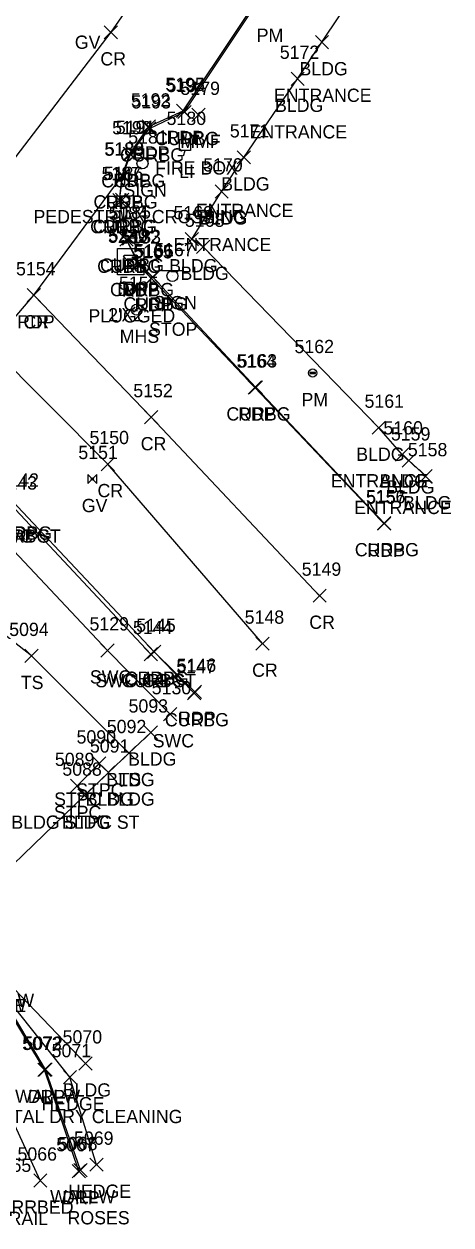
# Model space of a CAD drawing. Extents: x 1618146 to 1620418, y 640749 to 641927.
# Drawn here: x 1620347.9 to 1620412.3, y 640855.4 to 641036.5 of the extents above; entities that cross this region are included whole.
import ezdxf

# ---------------------------------------------------------------- set-up
doc = ezdxf.new("R2010")
doc.units = 0
for name, color, linetype in [('D_A', 7, 'Continuous'), ('D_C', 7, 'Continuous'), ('D_I', 7, 'Continuous'), ('D_TIC', 7, 'Continuous'), ('DS', 7, 'Continuous'), ('L_A', 7, 'Continuous'), ('L_C', 7, 'Continuous'), ('L_I', 7, 'Continuous'), ('L_TIC', 7, 'Continuous'), ('LAHR', 7, 'Continuous'), ('LBC', 7, 'Continuous'), ('LBF', 7, 'Continuous'), ('LELB', 7, 'Continuous'), ('LW', 7, 'Continuous'), ('P_A', 7, 'Continuous'), ('P_I', 7, 'Continuous'), ('P_TIC', 7, 'Continuous'), ('PET', 7, 'Continuous'), ('PRC', 7, 'Continuous'), ('R_A', 7, 'Continuous'), ('R_I', 7, 'Continuous'), ('R_TIC', 7, 'Continuous'), ('RC', 7, 'Continuous'), ('RDP', 7, 'Continuous'), ('RRB', 7, 'Continuous'), ('RSW', 7, 'Continuous'), ('S_A', 7, 'Continuous'), ('S_C', 7, 'Continuous'), ('S_I', 7, 'Continuous'), ('SPM', 7, 'Continuous'), ('SSGN', 7, 'Continuous'), ('U_A', 7, 'Continuous'), ('U_I', 7, 'Continuous'), ('ULP', 7, 'Continuous'), ('USMH', 7, 'Continuous'), ('UWV', 7, 'Continuous')]:
    doc.layers.add(name, color=color, linetype=linetype)

msp = doc.modelspace()

# ---------------------------------------------------------------- linework, layer by layer
at = {"layer": 'D_TIC'}
for points in [[(1620362.87, 640999.49), (1620364.87, 641001.49)], [(1620364.87, 640999.49), (1620362.87, 641001.49)]]:
    msp.add_lwpolyline(points, dxfattribs=at)
at = {"layer": 'DS'}
for p, q in [((1620362.02, 641002.65), (1620366.02, 641002.65)), ((1620362.02, 640998.65), (1620362.02, 641002.65)), ((1620366.02, 641002.65), (1620366.02, 640998.65)), ((1620363.02, 640999.65), (1620363.02, 641001.65)), ((1620363.02, 641001.65), (1620365.02, 641001.65)), ((1620364.03, 641000.65), (1620364.03, 641000.65)), ((1620364.03, 641000.65), (1620364.03, 641000.65)), ((1620365.02, 641001.65), (1620365.02, 640999.65)), ((1620365.02, 640999.65), (1620363.02, 640999.65)), ((1620366.02, 640998.65), (1620362.02, 640998.65))]:
    msp.add_line(p, q, dxfattribs=at)
at = {"layer": 'L_TIC'}
for points in [[(1620391.85, 641032.74), (1620393.85, 641034.74)], [(1620393.85, 641032.74), (1620391.85, 641034.74)], [(1620388.18, 641027.23), (1620390.18, 641029.23)], [(1620390.18, 641027.23), (1620388.18, 641029.23)], [(1620373.22, 641021.79), (1620375.22, 641023.79)], [(1620375.22, 641021.79), (1620373.22, 641023.79)], [(1620380.08, 641015.38), (1620382.08, 641017.38)], [(1620382.08, 641015.38), (1620380.08, 641017.38)], [(1620376.73, 641010.25), (1620378.73, 641012.25)], [(1620378.73, 641010.25), (1620376.73, 641012.25)], [(1620372.23, 641003.05), (1620374.23, 641005.05)], [(1620374.23, 641003.05), (1620372.23, 641005.05)], [(1620373.93, 641001.91), (1620375.93, 641003.91)], [(1620375.93, 641001.91), (1620373.93, 641003.91)], [(1620400.43, 640974.63), (1620402.43, 640976.63)], [(1620402.43, 640974.63), (1620400.43, 640976.63)], [(1620403.94, 640970.61), (1620405.94, 640972.61)], [(1620405.94, 640970.61), (1620403.94, 640972.61)], [(1620404.94, 640969.7), (1620406.94, 640971.7)], [(1620406.94, 640969.7), (1620404.94, 640971.7)], [(1620407.48, 640967.32), (1620409.48, 640969.32)], [(1620409.48, 640967.32), (1620407.48, 640969.32)], [(1620348.05, 640940.23), (1620350.05, 640942.23)], [(1620350.05, 640940.23), (1620348.05, 640942.23)], [(1620366.04, 640928.69), (1620368.04, 640930.69)], [(1620368.04, 640928.69), (1620366.04, 640930.69)], [(1620362.76, 640925.59), (1620364.76, 640927.59)], [(1620364.76, 640925.59), (1620362.76, 640927.59)], [(1620362.76, 640925.59), (1620364.76, 640927.59)], [(1620364.76, 640925.59), (1620362.76, 640927.59)], [(1620358.29, 640924.02), (1620360.29, 640926.02)], [(1620360.29, 640924.02), (1620358.29, 640926.02)], [(1620359.65, 640922.65), (1620361.65, 640924.65)], [(1620361.65, 640922.65), (1620359.65, 640924.65)], [(1620359.65, 640922.65), (1620361.65, 640924.65)], [(1620361.65, 640922.65), (1620359.65, 640924.65)], [(1620354.94, 640920.64), (1620356.94, 640922.64)], [(1620356.94, 640920.64), (1620354.94, 640922.64)], [(1620356.06, 640919.17), (1620358.06, 640921.17)], [(1620358.06, 640919.17), (1620356.06, 640921.17)], [(1620356.06, 640919.17), (1620358.06, 640921.17)], [(1620358.06, 640919.17), (1620356.06, 640921.17)], [(1620350.18, 640877.87), (1620352.18, 640879.87)], [(1620352.18, 640877.87), (1620350.18, 640879.87)], [(1620356.19, 640878.8), (1620358.19, 640880.8)], [(1620358.19, 640878.8), (1620356.19, 640880.8)], [(1620353.87, 640876.73), (1620355.87, 640878.73)], [(1620355.87, 640876.73), (1620353.87, 640878.73)], [(1620357.88, 640863.54), (1620359.88, 640865.54)], [(1620359.88, 640863.54), (1620357.88, 640865.54)], [(1620355.45, 640862.73), (1620357.45, 640864.73)], [(1620357.45, 640862.73), (1620355.45, 640864.73)]]:
    msp.add_lwpolyline(points, dxfattribs=at)
at = {"layer": 'LAHR'}
msp.add_lwpolyline([(1620358.88, 640864.54), (1620354.87, 640877.73), (1620343.03, 640892.53)], dxfattribs=at)
at = {"layer": 'LBC'}
for points in [[(1620408.48, 640968.32), (1620405.94, 640970.7), (1620404.94, 640971.61), (1620401.43, 640975.63), (1620374.93, 641002.91), (1620373.23, 641004.05), (1620377.73, 641011.25), (1620381.08, 641016.38), (1620389.18, 641028.23), (1620392.85, 641033.74), (1620400.72, 641045.56), (1620404.21, 641050.79), (1620408.66, 641057.75)], [(1620357.19, 640879.8), (1620344.24, 640893.33), (1620344.13, 640893.45), (1620337.08, 640900.88), (1620357.06, 640920.17), (1620360.65, 640923.65), (1620363.76, 640926.59), (1620367.04, 640929.69)]]:
    msp.add_lwpolyline(points, dxfattribs=at)
at = {"layer": 'LBF'}
msp.add_lwpolyline([(1620357.06, 640920.17), (1620355.94, 640921.64), (1620359.29, 640925.02), (1620360.65, 640923.65)], dxfattribs=at)
at = {"layer": 'LELB'}
msp.add_lwpolyline([(1620363.76, 640926.59), (1620349.05, 640941.23), (1620337.14, 640950.53)], dxfattribs=at)
at = {"layer": 'LW'}
msp.add_lwpolyline([(1620356.45, 640863.73), (1620351.18, 640878.87), (1620343.03, 640892.53), (1620344.24, 640893.33)], dxfattribs=at)
at = {"layer": 'P_TIC'}
for points in [[(1620360.02, 641034.23), (1620362.02, 641036.23)], [(1620362.02, 641034.23), (1620360.02, 641036.23)], [(1620370.94, 641022.38), (1620372.94, 641024.38)], [(1620372.94, 641022.38), (1620370.94, 641024.38)], [(1620365.74, 641020.04), (1620367.74, 641022.04)], [(1620367.74, 641020.04), (1620365.74, 641022.04)], [(1620362.9, 641015.91), (1620364.9, 641017.91)], [(1620364.9, 641015.91), (1620362.9, 641017.91)], [(1620361.74, 641012.62), (1620363.74, 641014.62)], [(1620363.74, 641012.62), (1620361.74, 641014.62)], [(1620361.74, 641012.62), (1620363.74, 641014.62)], [(1620363.74, 641012.62), (1620361.74, 641014.62)], [(1620361.32, 641008.94), (1620363.32, 641010.94)], [(1620363.32, 641008.94), (1620361.32, 641010.94)], [(1620362.39, 641002.97), (1620364.39, 641004.97)], [(1620364.39, 641002.97), (1620362.39, 641004.97)], [(1620364.19, 640999.38), (1620366.19, 641001.38)], [(1620366.19, 640999.38), (1620364.19, 641001.38)], [(1620366.13, 640997.15), (1620368.13, 640999.15)], [(1620368.13, 640997.15), (1620366.13, 640999.15)], [(1620348.43, 640994.59), (1620350.43, 640996.59)], [(1620350.43, 640994.59), (1620348.43, 640996.59)], [(1620348.43, 640994.59), (1620350.43, 640996.59)], [(1620350.43, 640994.59), (1620348.43, 640996.59)], [(1620381.71, 640980.68), (1620383.71, 640982.68)], [(1620383.71, 640980.68), (1620381.71, 640982.68)], [(1620366.1, 640976.22), (1620368.1, 640978.22)], [(1620368.1, 640976.22), (1620366.1, 640978.22)], [(1620359.59, 640969.15), (1620361.59, 640971.15)], [(1620361.59, 640969.15), (1620359.59, 640971.15)], [(1620401.21, 640960.16), (1620403.21, 640962.16)], [(1620403.21, 640960.16), (1620401.21, 640962.16)], [(1620391.5, 640949.31), (1620393.5, 640951.31)], [(1620393.5, 640949.31), (1620391.5, 640951.31)], [(1620366.54, 640940.86), (1620368.54, 640942.86)], [(1620368.54, 640940.86), (1620366.54, 640942.86)], [(1620382.89, 640942.08), (1620384.89, 640944.08)], [(1620384.89, 640942.08), (1620382.89, 640944.08)], [(1620372.7, 640934.83), (1620374.7, 640936.83)], [(1620374.7, 640934.83), (1620372.7, 640936.83)]]:
    msp.add_lwpolyline(points, dxfattribs=at)
at = {"layer": 'PET'}
for points in [[(1620301.6, 640941.89), (1620306.67, 640947.65), (1620308.05, 640949.03), (1620313.72, 640955.55), (1620317.97, 640960.23), (1620327.2, 640970.29), (1620342.84, 640987.93), (1620349.43, 640995.59), (1620362.74, 641013.62), (1620363.9, 641016.91), (1620366.74, 641021.04), (1620371.94, 641023.38), (1620397.59, 641061.89), (1620399.29, 641063.9)], [(1620402.21, 640961.16), (1620382.71, 640981.68), (1620367.13, 640998.15), (1620365.19, 641000.38), (1620363.39, 641003.97), (1620362.32, 641009.94), (1620362.74, 641013.62)], [(1620327.2, 640970.29), (1620330.45, 640972.78), (1620333.39, 640973.27), (1620335.69, 640973.14), (1620337.31, 640972.69), (1620340.81, 640970.42), (1620346.94, 640963.75), (1620367.54, 640941.86), (1620373.7, 640935.83)]]:
    msp.add_lwpolyline(points, dxfattribs=at)
at = {"layer": 'PRC'}
for points in [[(1620386.4, 641071.71), (1620361.02, 641035.23), (1620336.24, 641002.91), (1620316.22, 640977.17), (1620300.32, 640960.31), (1620296.61, 640956.78), (1620272.86, 640927.85), (1620252.18, 640901.58), (1620233.9, 640877.59)], [(1620392.5, 640950.31), (1620367.1, 640977.22), (1620349.43, 640995.59)], [(1620383.89, 640943.08), (1620360.59, 640970.15), (1620342.84, 640987.93)]]:
    msp.add_lwpolyline(points, dxfattribs=at)
at = {"layer": 'R_TIC'}
for points in [[(1620371.11, 641022.22), (1620373.11, 641024.22)], [(1620373.11, 641022.22), (1620371.11, 641024.22)], [(1620365.83, 641019.75), (1620367.83, 641021.75)], [(1620367.83, 641019.75), (1620365.83, 641021.75)], [(1620363, 641015.85), (1620365, 641017.85)], [(1620365, 641015.85), (1620363, 641017.85)], [(1620361.82, 641012.67), (1620363.82, 641014.67)], [(1620363.82, 641012.67), (1620361.82, 641014.67)], [(1620361.32, 641008.94), (1620363.32, 641010.94)], [(1620363.32, 641008.94), (1620361.32, 641010.94)], [(1620361.72, 641008.97), (1620363.72, 641010.97)], [(1620363.72, 641008.97), (1620361.72, 641010.97)], [(1620362.39, 641002.97), (1620364.39, 641004.97)], [(1620364.39, 641002.97), (1620362.39, 641004.97)], [(1620362.81, 641003.14), (1620364.81, 641005.14)], [(1620364.81, 641003.14), (1620362.81, 641005.14)], [(1620364.32, 640999.45), (1620366.32, 641001.45)], [(1620366.32, 640999.45), (1620364.32, 641001.45)], [(1620366.34, 640997.3), (1620368.34, 640999.3)], [(1620368.34, 640997.3), (1620366.34, 640999.3)], [(1620381.87, 640980.71), (1620383.87, 640982.71)], [(1620383.87, 640980.71), (1620381.87, 640982.71)], [(1620401.22, 640960.24), (1620403.22, 640962.24)], [(1620403.22, 640960.24), (1620401.22, 640962.24)], [(1620359.51, 640941.06), (1620361.51, 640943.06)], [(1620361.51, 640941.06), (1620359.51, 640943.06)], [(1620366.54, 640940.86), (1620368.54, 640942.86)], [(1620368.54, 640940.86), (1620366.54, 640942.86)], [(1620366.05, 640940.51), (1620368.05, 640942.51)], [(1620368.05, 640940.51), (1620366.05, 640942.51)], [(1620366.05, 640940.51), (1620368.05, 640942.51)], [(1620368.05, 640940.51), (1620366.05, 640942.51)], [(1620372.58, 640934.61), (1620374.58, 640936.61)], [(1620374.58, 640934.61), (1620372.58, 640936.61)], [(1620368.97, 640931.44), (1620370.97, 640933.44)], [(1620370.97, 640931.44), (1620368.97, 640933.44)], [(1620350.01, 640877.82), (1620352.01, 640879.82)], [(1620352.01, 640877.82), (1620350.01, 640879.82)], [(1620349.4, 640861.15), (1620351.4, 640863.15)], [(1620351.4, 640861.15), (1620349.4, 640863.15)], [(1620355.19, 640862.55), (1620357.19, 640864.55)], [(1620357.19, 640862.55), (1620355.19, 640864.55)]]:
    msp.add_lwpolyline(points, dxfattribs=at)
at = {"layer": 'RC'}
for points in [[(1620362.72, 641009.97), (1620362.32, 641009.94), (1620362.82, 641013.67), (1620364, 641016.85), (1620366.83, 641020.75), (1620372.11, 641023.22), (1620397.73, 641061.74), (1620399.29, 641063.9), (1620399.42, 641063.74)], [(1620402.22, 640961.24), (1620382.87, 640981.71), (1620367.34, 640998.3), (1620365.32, 641000.45), (1620363.39, 641003.97), (1620363.81, 641004.14)], [(1620367.05, 640941.51), (1620367.54, 640941.86), (1620373.58, 640935.61)]]:
    msp.add_lwpolyline(points, dxfattribs=at)
at = {"layer": 'RDP'}
msp.add_lwpolyline([(1620356.19, 640863.55), (1620351.01, 640878.82), (1620342.67, 640892.6), (1620344.13, 640893.45)], dxfattribs=at)
at = {"layer": 'RRB'}
msp.add_lwpolyline([(1620350.4, 640862.15), (1620333.7, 640898.49), (1620311.06, 640944.94)], dxfattribs=at)
at = {"layer": 'RSW'}
for points in [[(1620308.05, 640949.03), (1620311.06, 640944.94), (1620322.85, 640957.65), (1620323.38, 640958.18), (1620330.34, 640965.74), (1620332.11, 640966.82), (1620333.44, 640967.5), (1620336.86, 640966.1), (1620338.93, 640962.95), (1620340.87, 640962.9), (1620360.51, 640942.06), (1620369.97, 640932.44)], [(1620346.65, 640963.3), (1620367.05, 640941.51)]]:
    msp.add_lwpolyline(points, dxfattribs=at)
at = {"layer": 'SPM'}
msp.add_lwpolyline([(1620391.03, 640983.78), (1620391.86, 640983.78), (1620391.86, 640983.95), (1620391.03, 640983.95)], close=True, dxfattribs=at)
msp.add_circle((1620391.45, 640983.87), 0.625, dxfattribs=at)
at = {"layer": 'SSGN'}
for p, q in [((1620364.15, 641016.3), (1620367.48, 641016.3)), ((1620365.8, 641015.47), (1620365.8, 641015.47)), ((1620368.67, 640999.33), (1620372, 640999.33)), ((1620370.31, 640998.5), (1620370.31, 640998.5))]:
    msp.add_line(p, q, dxfattribs=at)
for centre in [(1620365.8, 641015.47), (1620370.31, 640998.5)]:
    msp.add_circle(centre, 0.833, dxfattribs=at)
at = {"layer": 'ULP'}
for p, q in [((1620371.38, 641017.43), (1620371.38, 641019.09)), ((1620371.38, 641019.09), (1620373.05, 641019.09)), ((1620372.38, 641019.93), (1620372.21, 641019.09)), ((1620373.05, 641019.09), (1620373.05, 641017.43)), ((1620373.05, 641017.43), (1620371.38, 641017.43)), ((1620371.96, 641016.59), (1620372.21, 641017.43)), ((1620372.21, 641018.26), (1620372.21, 641018.26))]:
    msp.add_line(p, q, dxfattribs=at)
at = {"layer": 'USMH'}
for p, q in [((1620364.94, 640993.42), (1620364.94, 640993.42)), ((1620365.78, 640993.42), (1620365.78, 640993.42))]:
    msp.add_line(p, q, dxfattribs=at)
msp.add_circle((1620364.94, 640993.42), 0.833, dxfattribs=at)
at = {"layer": 'UWV'}
for p, q in [((1620357.58, 640968.57), (1620358.92, 640967.23)), ((1620358.92, 640968.57), (1620357.58, 640967.23))]:
    msp.add_line(p, q, dxfattribs=at)
for points in [[(1620357.58, 640968.57), (1620357.58, 640967.23)], [(1620358.92, 640967.23), (1620358.92, 640968.57)]]:
    msp.add_lwpolyline(points, dxfattribs=at)
msp.add_circle((1620358.25, 640967.9), 0.167, dxfattribs=at)

# ---------------------------------------------------------------- texts
at = {"layer": 'D_A'}
for s, p in [('DIB', (1620361.97, 640995.49)), ('DI', (1620363.08, 640995.65))]:
    msp.add_text(s, height=2, dxfattribs=at).set_placement(p)
at = {"layer": 'D_C'}
for s, p in [('PLUGGED', (1620357.65, 640991.49)), ("2'X2'", (1620360.63, 640991.65))]:
    msp.add_text(s, height=2, dxfattribs=at).set_placement(p)
at = {"layer": 'D_I'}
for s, p in [('5239', (1620360.6, 641003.49)), ('5240', (1620360.68, 641003.65))]:
    msp.add_text(s, height=2, dxfattribs=at).set_placement(p)
at = {"layer": 'L_A'}
for s, p in [('BLDG', (1620389.45, 641028.74)), ('BLDG', (1620385.77, 641023.23)), ('MMF', (1620371.5, 641017.79)), ('BLDG', (1620377.67, 641011.38)), ('BLDG', (1620374.32, 641006.25)), ('BLDG', (1620369.82, 640999.05)), ('BLDG', (1620371.52, 640997.91)), ('BLDG', (1620398.02, 640970.63)), ('BLDG', (1620401.53, 640966.61)), ('BLDG', (1620402.53, 640965.7)), ('BLDG', (1620405.07, 640963.32)), ('TS', (1620347.46, 640936.23)), ('BLDG', (1620363.63, 640924.69)), ('BLDG', (1620360.35, 640921.59)), ('TS', (1620362.17, 640921.59)), ('STPC', (1620355.8, 640920.02)), ('STPC BLDG', (1620352.48, 640918.65)), ('BLDG', (1620357.24, 640918.65)), ('STPC', (1620352.46, 640916.64)), ('BLDG STPC ST', (1620346.03, 640915.17)), ('BLDG', (1620353.65, 640915.17)), ('WALLW', (1620339.66, 640888.33)), ('WALLW', (1620338.45, 640887.53)), ('HEDGE', (1620338.73, 640887.53)), ('WALLW', (1620346.6, 640873.87)), ('BLDG', (1620353.78, 640874.8)), ('HEDGE', (1620350.57, 640872.73)), ('HEDGE', (1620354.58, 640859.54)), ('WALLW', (1620351.87, 640858.73))]:
    msp.add_text(s, height=2, dxfattribs=at).set_placement(p)
at = {"layer": 'L_C'}
for s, p in [('ENTRANCE', (1620385.61, 641024.74)), ('ENTRANCE', (1620381.93, 641019.23)), ('FIRE BOX', (1620367.7, 641013.79)), ('ENTRANCE', (1620373.84, 641007.38)), ('ENTRANCE', (1620370.49, 641002.25)), ('ENTRANCE', (1620394.19, 640966.63)), ('ENTRANCE', (1620397.69, 640962.61)), ('CAPITAL DRY CLEANING', (1620339.87, 640870.8)), ('ROSES', (1620354.5, 640855.54))]:
    msp.add_text(s, height=2, dxfattribs=at).set_placement(p)
at = {"layer": 'L_I'}
for s, p in [('5172', (1620386.49, 641031.23)), ('5179', (1620371.52, 641025.79)), ('5171', (1620378.96, 641019.38)), ('5170', (1620374.95, 641014.25)), ('5169', (1620370.48, 641007.05)), ('5168', (1620372.19, 641005.91)), ('5161', (1620399.26, 640978.63)), ('5160', (1620402.11, 640974.61)), ('5159', (1620403.24, 640973.7)), ('5158', (1620405.79, 640971.32)), ('5094', (1620345.71, 640944.23)), ('5093', (1620363.7, 640932.69)), ('5090', (1620355.86, 640928.02)), ('5092', (1620360.42, 640929.59)), ('5092', (1620360.42, 640929.59)), ('5091', (1620357.87, 640926.65)), ('5091', (1620357.87, 640926.65)), ('5089', (1620352.6, 640924.64)), ('5088', (1620353.72, 640923.17)), ('5088', (1620353.72, 640923.17)), ('5070', (1620353.76, 640882.8)), ('5072', (1620347.84, 640881.87)), ('5071', (1620352.1, 640880.73)), ('5068', (1620353.06, 640866.73)), ('5069', (1620355.48, 640867.54))]:
    msp.add_text(s, height=2, dxfattribs=at).set_placement(p)
at = {"layer": 'P_A'}
for s, p in [('CR', (1620359.45, 641030.23)), ('RDP', (1620369.42, 641018.38)), ('RDP', (1620364.22, 641016.04)), ('RDP', (1620361.39, 641011.91)), ('RDP', (1620360.23, 641008.62)), ('RDP', (1620360.23, 641008.62)), ('RDP', (1620359.81, 641004.94)), ('RDP', (1620360.87, 640998.97)), ('RDP', (1620362.68, 640995.38)), ('RDP', (1620364.62, 640993.15)), ('RDP', (1620346.92, 640990.59)), ('CR', (1620347.86, 640990.59)), ('RDP', (1620380.2, 640976.68)), ('CR', (1620365.53, 640972.22)), ('CR', (1620359.02, 640965.15)), ('RDP', (1620344.42, 640958.75)), ('RDP', (1620399.69, 640956.16)), ('CR', (1620390.93, 640945.31)), ('CR', (1620382.32, 640938.08)), ('RDP', (1620365.03, 640936.86)), ('RDP', (1620371.19, 640930.83))]:
    msp.add_text(s, height=2, dxfattribs=at).set_placement(p)
at = {"layer": 'P_I'}
for s, p in [('5195', (1620369.24, 641026.38)), ('5192', (1620364.04, 641024.04)), ('5191', (1620361.78, 641019.91)), ('5188', (1620360.05, 641016.62)), ('5188', (1620360.05, 641016.62)), ('5187', (1620359.63, 641012.94)), ('5184', (1620360.69, 641006.97)), ('5182', (1620362.49, 641003.38)), ('5165', (1620364.39, 641001.15)), ('5154', (1620346.74, 640998.59)), ('5154', (1620346.74, 640998.59)), ('5164', (1620379.97, 640984.68)), ('5152', (1620364.41, 640980.22)), ('5150', (1620357.81, 640973.15)), ('5142', (1620344.24, 640966.75)), ('5157', (1620399.51, 640964.16)), ('5149', (1620389.8, 640953.31)), ('5148', (1620381.2, 640946.08)), ('5145', (1620364.85, 640944.86)), ('5146', (1620370.96, 640938.83))]:
    msp.add_text(s, height=2, dxfattribs=at).set_placement(p)
at = {"layer": 'R_A'}
for s, p in [('CURBG', (1620367.69, 641018.22)), ('CURBG', (1620362.41, 641015.75)), ('CURBG', (1620359.58, 641011.85)), ('CURBG', (1620358.41, 641008.67)), ('CURBG', (1620357.91, 641004.94)), ('CURBG', (1620358.31, 641004.97)), ('CURBG', (1620358.97, 640998.97)), ('CURBG', (1620359.39, 640999.14)), ('CURBG', (1620360.9, 640995.45)), ('CURBG', (1620362.93, 640993.3)), ('CURBG', (1620378.45, 640976.71)), ('CURBG', (1620342.52, 640958.75)), ('CG SWC ST', (1620338.31, 640958.3)), ('CURBG', (1620342.23, 640958.3)), ('CURBG', (1620397.8, 640956.24)), ('SWC', (1620357.87, 640937.06)), ('SWC CG ST', (1620358.71, 640936.51)), ('CURBG', (1620362.63, 640936.51)), ('CURBG', (1620363.12, 640936.86)), ('CURBG', (1620369.17, 640930.61)), ('SWC', (1620367.33, 640927.44)), ('DRP', (1620348.5, 640873.82)), ('DRP', (1620353.68, 640858.55)), ('RRBED', (1620346.04, 640857.15)), ('RRRAIL', (1620341.76, 640855.45))]:
    msp.add_text(s, height=2, dxfattribs=at).set_placement(p)
at = {"layer": 'R_I'}
for s, p in [('5194', (1620369.41, 641026.22)), ('5193', (1620364.14, 641023.75)), ('5190', (1620361.22, 641019.85)), ('5189', (1620360.12, 641016.67)), ('5187', (1620359.63, 641012.94)), ('5186', (1620359.97, 641012.97)), ('5184', (1620360.69, 641006.97)), ('5185', (1620361.12, 641007.14)), ('5183', (1620362.63, 641003.45)), ('5166', (1620364.55, 641001.3)), ('5163', (1620380.13, 640984.71)), ('5143', (1620343.96, 640966.3)), ('5143', (1620343.96, 640966.3)), ('5142', (1620344.24, 640966.75)), ('5156', (1620399.47, 640964.24)), ('5129', (1620357.81, 640945.06)), ('5144', (1620364.36, 640944.51)), ('5144', (1620364.36, 640944.51)), ('5145', (1620364.85, 640944.86)), ('5147', (1620370.89, 640938.61)), ('5130', (1620367.19, 640935.44)), ('5073', (1620347.67, 640881.82)), ('5067', (1620352.8, 640866.55)), ('5066', (1620346.96, 640865.15)), ('5065', (1620343.08, 640863.45))]:
    msp.add_text(s, height=2, dxfattribs=at).set_placement(p)
at = {"layer": 'S_A'}
for s, p in [('PM', (1620383.01, 641033.79)), ('SIGN', (1620362.93, 641010.45)), ('SIGN', (1620367.45, 640993.48)), ('PM', (1620389.76, 640978.87))]:
    msp.add_text(s, height=2, dxfattribs=at).set_placement(p)
at = {"layer": 'S_C'}
for s, p in [('PEDESTRIAN CROSSING', (1620349.37, 641006.45)), ('STOP', (1620366.78, 640989.48))]:
    msp.add_text(s, height=2, dxfattribs=at).set_placement(p)
at = {"layer": 'S_I'}
for s, p in [('5181', (1620363.65, 641018.45)), ('5167', (1620367.56, 641001.48)), ('5162', (1620388.71, 640986.87))]:
    msp.add_text(s, height=2, dxfattribs=at).set_placement(p)
at = {"layer": 'U_A'}
for s, p in [('GV', (1620355.6, 641032.74)), ('LI', (1620371.32, 641013.26)), ('MHS', (1620362.36, 640988.42)), ('GV', (1620356.65, 640962.9))]:
    msp.add_text(s, height=2, dxfattribs=at).set_placement(p)
at = {"layer": 'U_I'}
for s, p in [('5180', (1620369.43, 641021.26)), ('5155', (1620362.25, 640996.42)), ('5151', (1620356.13, 640970.9))]:
    msp.add_text(s, height=2, dxfattribs=at).set_placement(p)

doc.saveas('drawing.dxf')
